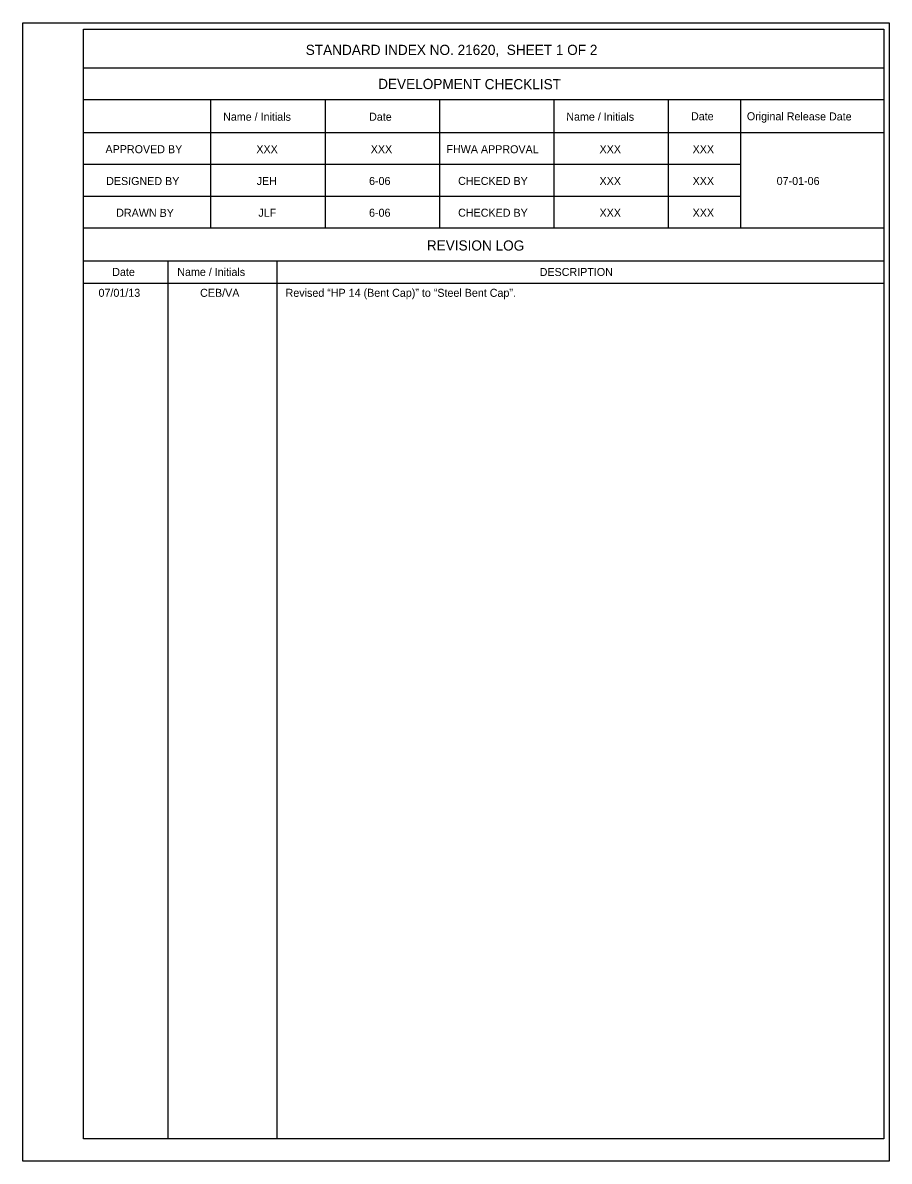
# Model space of a CAD drawing. Extents: x 115718.2 to 115735.9, y 111778.7 to 111787.4.
# Drawn here: x 115730.4 to 115735.85, y 111780.26 to 111787.43 of the extents above; entities that cross this region are included whole.
import ezdxf

# ---------------------------------------------------------------- set-up
doc = ezdxf.new("R2010")
doc.units = 0
for name, color, linetype in [('Border', 7, 'Continuous'), ('PlotBorder_dp', 7, 'Continuous'), ('TextStructures', 7, 'Continuous')]:
    doc.layers.add(name, color=color, linetype=linetype)

msp = doc.modelspace()

# ---------------------------------------------------------------- linework, layer by layer
at = {"layer": 'Border'}
for p, q in [((115735.821, 111787.1406), (115730.7842, 111787.1406)), ((115735.821, 111786.9406), (115730.7842, 111786.9406)), ((115731.5842, 111786.9406), (115731.5842, 111786.1336)), ((115732.3042, 111786.9406), (115732.3042, 111786.1336)), ((115733.0242, 111786.9406), (115733.0242, 111786.1336)), ((115733.7442, 111786.9406), (115733.7442, 111786.1336)), ((115734.4642, 111786.9406), (115734.4642, 111786.1336)), ((115734.918, 111786.9406), (115734.918, 111786.1336)), ((115735.821, 111786.7336), (115730.7842, 111786.7336)), ((115734.918, 111786.5336), (115730.7842, 111786.5336)), ((115734.918, 111786.3336), (115730.7842, 111786.3336)), ((115735.821, 111786.1336), (115730.7842, 111786.1336)), ((115735.821, 111785.9266), (115730.7842, 111785.9266)), ((115731.3143, 111785.9266), (115731.3143, 111780.4)), ((115731.9999, 111785.9266), (115731.9999, 111780.4)), ((115735.821, 111785.7857), (115730.7842, 111785.7857))]:
    msp.add_line(p, q, dxfattribs=at)
msp.add_lwpolyline([(115730.7843, 111787.3857), (115735.821, 111787.3857), (115735.821, 111780.4), (115730.7843, 111780.4)], close=True, dxfattribs=at)
at = {"layer": 'PlotBorder_dp'}
msp.add_line((115730.4016, 111780.2597), (115730.4016, 111780.2597), dxfattribs=at)
msp.add_lwpolyline([(115730.4016, 111787.4264), (115735.855, 111787.4264), (115735.855, 111780.2597), (115730.4016, 111780.2597)], close=True, dxfattribs=at)

# ---------------------------------------------------------------- texts
at = {"layer": 'TextStructures'}
for s, height, p in [('STANDARD INDEX NO. 21620,  SHEET 1 OF 2', 0.064, (115732.1826, 111787.2237)), ('XXX', 0.0504, (115731.8718, 111786.6053)), ('XXX', 0.0504, (115732.5918, 111786.6053)), ('XXX', 0.0504, (115734.0318, 111786.6053)), ('XXX', 0.0504, (115734.6176, 111786.6053)), ('JEH', 0.0504, (115731.8736, 111786.4053)), ('6-06', 0.0504, (115732.581, 111786.4053)), ('XXX', 0.0504, (115734.0318, 111786.4053)), ('XXX', 0.0504, (115734.6176, 111786.4053)), ('07-01-06', 0.0504, (115735.1466, 111786.4053)), ('JLF', 0.0504, (115731.8842, 111786.2053)), ('6-06', 0.0504, (115732.581, 111786.2053)), ('XXX', 0.0504, (115734.0318, 111786.2053)), ('XXX', 0.0504, (115734.6176, 111786.2053)), ('DESCRIPTION', 0.0504, (115733.6551, 111785.8324)), ('07/01/13', 0.0504, (115730.8784, 111785.7012)), ('CEB/VA', 0.0504, (115731.5178, 111785.7012)), ('Revised “HP 14 (Bent Cap)” to “Steel Bent Cap”.', 0.0504, (115732.0558, 111785.7012))]:
    msp.add_text(s, height=height, dxfattribs=at).set_placement(p)
for s, height, p in [('DEVELOPMENT CHECKLIST', 0.064, (115732.6382, 111787.0098)), ('Name / Initials', 0.0504, (115731.6624, 111786.8103)), ('Date', 0.0504, (115732.5811, 111786.8099)), ('Name / Initials', 0.0504, (115733.8224, 111786.8103)), ('Date', 0.0504, (115734.6073, 111786.8128)), ('Original Release Date', 0.0504, (115734.9589, 111786.8128)), ('APPROVED BY', 0.0504, (115730.9222, 111786.6058)), ('FHWA APPROVAL', 0.0504, (115733.068, 111786.6058)), ('DESIGNED BY', 0.0504, (115730.9264, 111786.4054)), ('CHECKED BY', 0.0504, (115733.1417, 111786.4058)), ('DRAWN BY', 0.0504, (115730.9896, 111786.2053)), ('CHECKED BY', 0.0504, (115733.1417, 111786.2058)), ('REVISION LOG', 0.064, (115732.9445, 111785.9933)), ('Date', 0.0504, (115730.9648, 111785.8326)), ('Name / Initials', 0.0504, (115731.374, 111785.833))]:
    msp.add_text(s, height=height, rotation=359.87563, dxfattribs=at).set_placement(p)

doc.saveas('drawing.dxf')
